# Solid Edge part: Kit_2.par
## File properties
Author: bmolnar
Last saved by: bmolnar
Revision: 78
Sűrűség: 0,000 kg/m^3
Pontosság: 0,990
Username: bmolnar
Dokumentum tartalom típus: 0
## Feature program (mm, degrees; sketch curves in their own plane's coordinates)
base feature "unnamed BaseFeature 1"
sketch for "unnamed Hole 1" plane through (44.5, 44.5, -94.5) normal (0, 0, -1) x-axis (-1, 0, 0)
  hole centre (0, 0) bore radius 4.188
hole "unnamed Hole 1" through
sketch for "unnamed Hole 2" plane through (44.5, 44.5, -94.5) normal (0, 0, -1) x-axis (-1, 0, 0)
  hole centre (89, 0) bore radius 4.188
hole "unnamed Hole 2" through
sketch for "unnamed Hole 3" plane through (44.5, 44.5, -94.5) normal (0, 0, -1) x-axis (-1, 0, 0)
  hole centre (89, -89) bore radius 4.188
hole "unnamed Hole 3" through
sketch for "unnamed Hole 4" plane through (44.5, 44.5, -94.5) normal (0, 0, -1) x-axis (-1, 0, 0)
  hole centre (0, -89) bore radius 4.188
hole "unnamed Hole 4" through
pattern "unnamed Pattern 1" of "unnamed Hole 1", "unnamed Hole 2", "unnamed Hole 3", "unnamed Hole 4"
sketch for "Furat_6" plane through (56.65, 0, -134.65) normal (-1, 0, 0) x-axis (0, 1, 0)
  hole centre (-0.0009, -47.65) bore radius 4.283
  dimension (linear) = 0.0009
hole "Furat_6" nominal diameter 9.728 finite  ThreadDepth = 12 mm
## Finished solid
Body 1: solid body, 320 faces, 792 edges, 492 vertices.
  Faces by surface: plane 145, cylinder 82, swept 56, cone 25, torus 11, spline 1
  Edges by curve: line 446, circle 180, spline 136, ellipse 28, curve on surface 2
Bounding box of the edges (mm; curved faces can reach further): 113.300 x 113.300 x 19.500, from (-56.65, -56.65, -97.5) to (56.65, 56.65, -78).
Cylindrical faces by radius (mm): R0.2 x48, R0.2006 x2, R0.2007 x2, R4.188 x4, R4.283 x1, R6.35 x4, R6.55 x4, R6.75 x4, R12.8 x1, R13.45 x1, R14 x1, R14.9 x1, R15 x1, R51.85 x8
Conical faces (half-angle, radius in mm at the cone's reference point): 0.5 deg R12.25 x4, 0.5 deg R35 x2, 3 deg R14.95 x1, 7 deg R14.2695 x1, 14 deg R12.65 x1, 14 deg R13.057 x1, 17 deg R12.65 x1, 23 deg R13.4211 x1, 42.5 deg R12.637 x1, 45 deg R4.185 x4, 45 deg R4.985 x4, 45 deg R13.6 x1, 84 deg R13.012 x1, 85 deg R14.6625 x1, 87 deg R12.7157 x1
Toroidal faces (ring radius, tube radius in mm): R6.05 r0.3 x2, R6.15 r0.2 x6, R13.4008 r0.225 x1, R13.8914 r0.325 x1, R14.7 r0.2 x1
Planar faces by outward normal: +x 17, +y 14, +z 2, -x 14, -y 16, -z 19, oblique 63
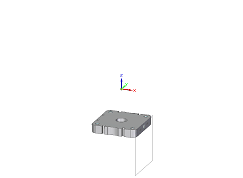
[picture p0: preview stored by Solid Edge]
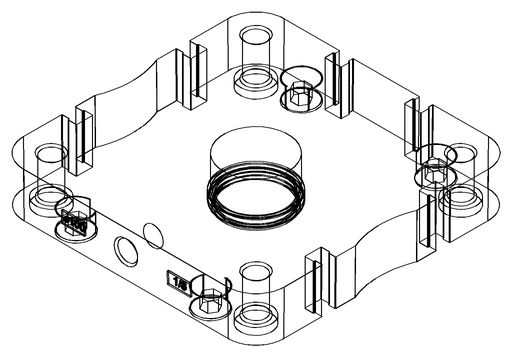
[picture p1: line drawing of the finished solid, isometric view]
